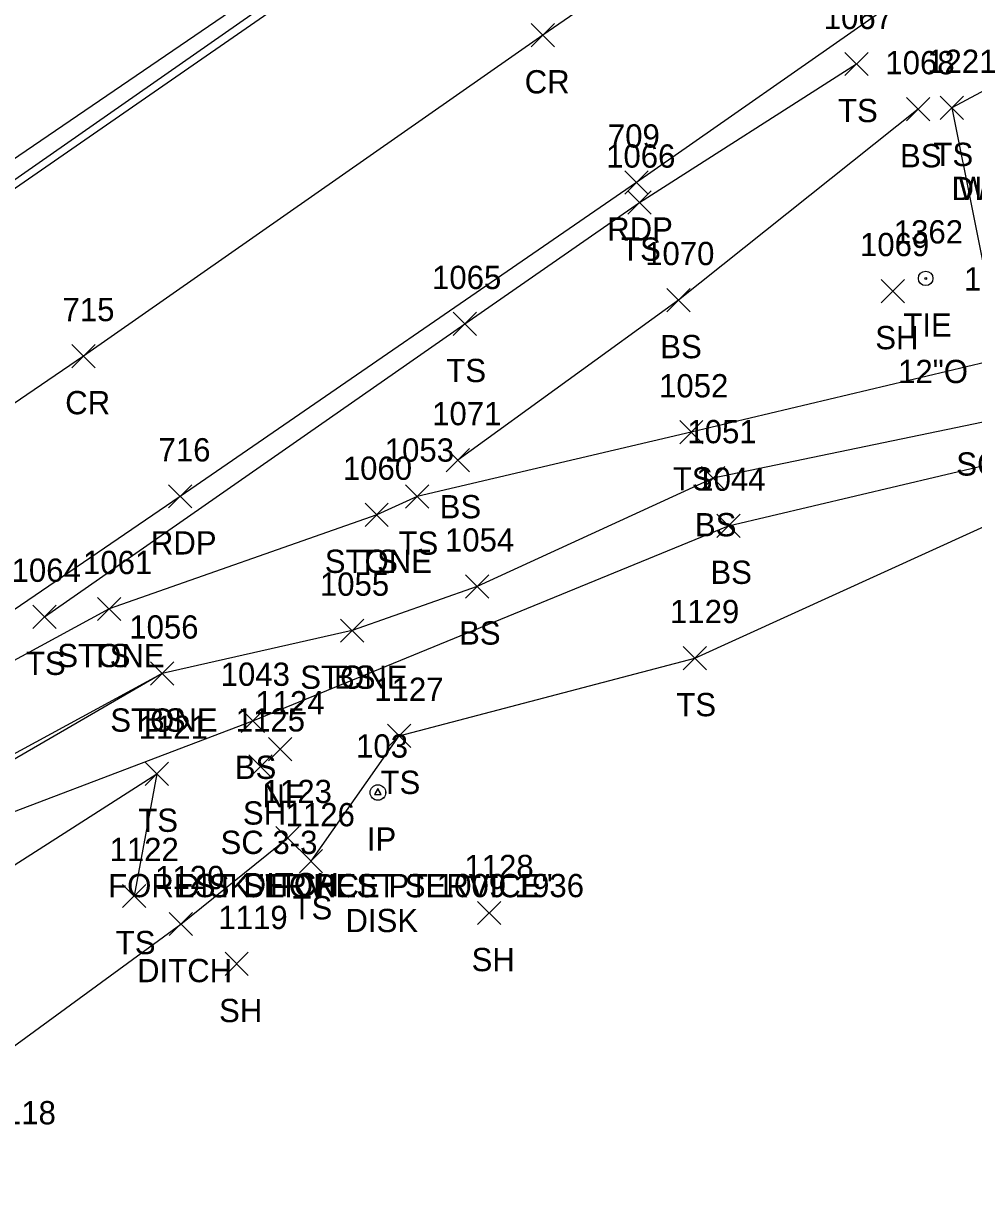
# Model space of a CAD drawing. Extents: x 1528286 to 1556263, y 492387 to 508952.
# Drawn here: x 1528862.6 to 1528944.2, y 492861.6 to 492961.3 of the extents above; entities that cross this region are included whole.
import ezdxf

# ---------------------------------------------------------------- set-up
doc = ezdxf.new("R2010")
doc.units = 0
for name, color, linetype in [('C_A', 7, 'Continuous'), ('C_C', 7, 'Continuous'), ('C_I', 7, 'Continuous'), ('CBP', 7, 'Continuous'), ('D_A', 7, 'Continuous'), ('D_I', 7, 'Continuous'), ('D_TIC', 7, 'Continuous'), ('DD', 7, 'Continuous'), ('L_A', 7, 'Continuous'), ('L_C', 7, 'Continuous'), ('L_I', 7, 'Continuous'), ('L_TIC', 7, 'Continuous'), ('LASF', 7, 'Continuous'), ('LELB', 7, 'Continuous'), ('M_A', 7, 'Continuous'), ('M_C', 7, 'Continuous'), ('M_I', 7, 'Continuous'), ('MPIR', 7, 'Continuous'), ('P_A', 7, 'Continuous'), ('P_I', 7, 'Continuous'), ('P_TIC', 7, 'Continuous'), ('PET', 7, 'Continuous'), ('PRC', 7, 'Continuous'), ('RGR', 7, 'Continuous')]:
    doc.layers.add(name, color=color, linetype=linetype)

msp = doc.modelspace()

# ---------------------------------------------------------------- linework, layer by layer
at = {"layer": 'CBP'}
for radius in [0.625, 0.625, 0.0833, 0.0833]:
    msp.add_circle((1528940.091, 492939.392), radius, dxfattribs=at)
at = {"layer": 'D_TIC'}
for points in [[(1528884.264, 492890.293), (1528886.264, 492892.293)], [(1528886.264, 492890.293), (1528884.264, 492892.293)], [(1528884.264, 492890.293), (1528886.264, 492892.293)], [(1528886.264, 492890.293), (1528884.264, 492892.293)], [(1528875.113, 492882.9), (1528877.113, 492884.9)], [(1528877.113, 492882.9), (1528875.113, 492884.9)], [(1528875.113, 492882.9), (1528877.113, 492884.9)], [(1528877.113, 492882.9), (1528875.113, 492884.9)]]:
    msp.add_lwpolyline(points, dxfattribs=at)
at = {"layer": 'DD'}
msp.add_lwpolyline([(1528821.309, 492845.775), (1528834.865, 492854.142), (1528847.183, 492864.422), (1528856.697, 492869.705), (1528876.113, 492883.9), (1528885.264, 492891.293)], dxfattribs=at)
msp.add_lwpolyline([(1528821.309, 492845.775), (1528834.865, 492854.142), (1528847.183, 492864.422), (1528856.697, 492869.705), (1528876.113, 492883.9), (1528885.264, 492891.293)], dxfattribs=at)
at = {"layer": 'L_TIC'}
for points in [[(1528933.15, 492956.819), (1528935.15, 492958.819)], [(1528935.15, 492956.819), (1528933.15, 492958.819)], [(1528933.15, 492956.819), (1528935.15, 492958.819)], [(1528935.15, 492956.819), (1528933.15, 492958.819)], [(1528938.445, 492952.934), (1528940.445, 492954.934)], [(1528940.445, 492952.934), (1528938.445, 492954.934)], [(1528938.445, 492952.934), (1528940.445, 492954.934)], [(1528940.445, 492952.934), (1528938.445, 492954.934)], [(1528941.345, 492953.048), (1528943.345, 492955.048)], [(1528943.345, 492953.048), (1528941.345, 492955.048)], [(1528941.345, 492953.048), (1528943.345, 492955.048)], [(1528943.345, 492953.048), (1528941.345, 492955.048)], [(1528914.515, 492944.908), (1528916.515, 492946.908)], [(1528916.515, 492944.908), (1528914.515, 492946.908)], [(1528914.515, 492944.908), (1528916.515, 492946.908)], [(1528916.515, 492944.908), (1528914.515, 492946.908)], [(1528917.851, 492936.528), (1528919.851, 492938.528)], [(1528919.851, 492936.528), (1528917.851, 492938.528)], [(1528917.851, 492936.528), (1528919.851, 492938.528)], [(1528919.851, 492936.528), (1528917.851, 492938.528)], [(1528936.271, 492937.301), (1528938.271, 492939.301)], [(1528938.271, 492937.301), (1528936.271, 492939.301)], [(1528936.271, 492937.301), (1528938.271, 492939.301)], [(1528938.271, 492937.301), (1528936.271, 492939.301)], [(1528899.505, 492934.476), (1528901.505, 492936.476)], [(1528901.505, 492934.476), (1528899.505, 492936.476)], [(1528899.505, 492934.476), (1528901.505, 492936.476)], [(1528901.505, 492934.476), (1528899.505, 492936.476)], [(1528918.959, 492925.163), (1528920.959, 492927.163)], [(1528920.959, 492925.163), (1528918.959, 492927.163)], [(1528918.959, 492925.163), (1528920.959, 492927.163)], [(1528920.959, 492925.163), (1528918.959, 492927.163)], [(1528898.899, 492922.769), (1528900.899, 492924.769)], [(1528900.899, 492922.769), (1528898.899, 492924.769)], [(1528898.899, 492922.769), (1528900.899, 492924.769)], [(1528900.899, 492922.769), (1528898.899, 492924.769)], [(1528920.827, 492921.221), (1528922.827, 492923.221)], [(1528922.827, 492921.221), (1528920.827, 492923.221)], [(1528920.827, 492921.221), (1528922.827, 492923.221)], [(1528922.827, 492921.221), (1528920.827, 492923.221)], [(1528895.398, 492919.638), (1528897.398, 492921.638)], [(1528897.398, 492919.638), (1528895.398, 492921.638)], [(1528895.398, 492919.638), (1528897.398, 492921.638)], [(1528897.398, 492919.638), (1528895.398, 492921.638)], [(1528891.931, 492918.077), (1528893.931, 492920.077)], [(1528893.931, 492918.077), (1528891.931, 492920.077)], [(1528891.931, 492918.077), (1528893.931, 492920.077)], [(1528893.931, 492918.077), (1528891.931, 492920.077)], [(1528891.931, 492918.077), (1528893.931, 492920.077)], [(1528893.931, 492918.077), (1528891.931, 492920.077)], [(1528891.931, 492918.077), (1528893.931, 492920.077)], [(1528893.931, 492918.077), (1528891.931, 492920.077)], [(1528922.156, 492917.133), (1528924.156, 492919.133)], [(1528924.156, 492917.133), (1528922.156, 492919.133)], [(1528922.156, 492917.133), (1528924.156, 492919.133)], [(1528924.156, 492917.133), (1528922.156, 492919.133)], [(1528900.569, 492911.915), (1528902.569, 492913.915)], [(1528902.569, 492911.915), (1528900.569, 492913.915)], [(1528900.569, 492911.915), (1528902.569, 492913.915)], [(1528902.569, 492911.915), (1528900.569, 492913.915)], [(1528868.957, 492909.976), (1528870.957, 492911.976)], [(1528870.957, 492909.976), (1528868.957, 492911.976)], [(1528868.957, 492909.976), (1528870.957, 492911.976)], [(1528870.957, 492909.976), (1528868.957, 492911.976)], [(1528868.957, 492909.976), (1528870.957, 492911.976)], [(1528870.957, 492909.976), (1528868.957, 492911.976)], [(1528868.957, 492909.976), (1528870.957, 492911.976)], [(1528870.957, 492909.976), (1528868.957, 492911.976)], [(1528863.389, 492909.31), (1528865.389, 492911.31)], [(1528865.389, 492909.31), (1528863.389, 492911.31)], [(1528863.389, 492909.31), (1528865.389, 492911.31)], [(1528865.389, 492909.31), (1528863.389, 492911.31)], [(1528889.826, 492908.115), (1528891.826, 492910.115)], [(1528891.826, 492908.115), (1528889.826, 492910.115)], [(1528889.826, 492908.115), (1528891.826, 492910.115)], [(1528891.826, 492908.115), (1528889.826, 492910.115)], [(1528889.826, 492908.115), (1528891.826, 492910.115)], [(1528891.826, 492908.115), (1528889.826, 492910.115)], [(1528889.826, 492908.115), (1528891.826, 492910.115)], [(1528891.826, 492908.115), (1528889.826, 492910.115)], [(1528919.262, 492905.759), (1528921.262, 492907.759)], [(1528921.262, 492905.759), (1528919.262, 492907.759)], [(1528919.262, 492905.759), (1528921.262, 492907.759)], [(1528921.262, 492905.759), (1528919.262, 492907.759)], [(1528873.507, 492904.431), (1528875.507, 492906.431)], [(1528875.507, 492904.431), (1528873.507, 492906.431)], [(1528873.507, 492904.431), (1528875.507, 492906.431)], [(1528875.507, 492904.431), (1528873.507, 492906.431)], [(1528873.507, 492904.431), (1528875.507, 492906.431)], [(1528875.507, 492904.431), (1528873.507, 492906.431)], [(1528873.507, 492904.431), (1528875.507, 492906.431)], [(1528875.507, 492904.431), (1528873.507, 492906.431)], [(1528881.303, 492900.371), (1528883.303, 492902.371)], [(1528883.303, 492900.371), (1528881.303, 492902.371)], [(1528881.303, 492900.371), (1528883.303, 492902.371)], [(1528883.303, 492900.371), (1528881.303, 492902.371)], [(1528893.852, 492899.077), (1528895.852, 492901.077)], [(1528895.852, 492899.077), (1528893.852, 492901.077)], [(1528893.852, 492899.077), (1528895.852, 492901.077)], [(1528895.852, 492899.077), (1528893.852, 492901.077)], [(1528883.638, 492897.92), (1528885.638, 492899.92)], [(1528885.638, 492897.92), (1528883.638, 492899.92)], [(1528883.638, 492897.92), (1528885.638, 492899.92)], [(1528885.638, 492897.92), (1528883.638, 492899.92)], [(1528881.95, 492896.447), (1528883.95, 492898.447)], [(1528883.95, 492896.447), (1528881.95, 492898.447)], [(1528881.95, 492896.447), (1528883.95, 492898.447)], [(1528883.95, 492896.447), (1528881.95, 492898.447)], [(1528873.04, 492895.82), (1528875.04, 492897.82)], [(1528875.04, 492895.82), (1528873.04, 492897.82)], [(1528873.04, 492895.82), (1528875.04, 492897.82)], [(1528875.04, 492895.82), (1528873.04, 492897.82)], [(1528886.291, 492888.3), (1528888.291, 492890.3)], [(1528888.291, 492888.3), (1528886.291, 492890.3)], [(1528886.291, 492888.3), (1528888.291, 492890.3)], [(1528888.291, 492888.3), (1528886.291, 492890.3)], [(1528871.111, 492885.309), (1528873.111, 492887.309)], [(1528873.111, 492885.309), (1528871.111, 492887.309)], [(1528871.111, 492885.309), (1528873.111, 492887.309)], [(1528873.111, 492885.309), (1528871.111, 492887.309)], [(1528901.596, 492883.846), (1528903.596, 492885.846)], [(1528903.596, 492883.846), (1528901.596, 492885.846)], [(1528901.596, 492883.846), (1528903.596, 492885.846)], [(1528903.596, 492883.846), (1528901.596, 492885.846)], [(1528879.904, 492879.468), (1528881.904, 492881.468)], [(1528881.904, 492879.468), (1528879.904, 492881.468)], [(1528879.904, 492879.468), (1528881.904, 492881.468)], [(1528881.904, 492879.468), (1528879.904, 492881.468)]]:
    msp.add_lwpolyline(points, dxfattribs=at)
at = {"layer": 'LASF'}
for points in [[(1528892.931, 492919.077), (1528869.957, 492910.976), (1528843.058, 492896.384), (1528834.233, 492890.275)], [(1528892.931, 492919.077), (1528869.957, 492910.976), (1528843.058, 492896.384), (1528834.233, 492890.275)], [(1528890.826, 492909.115), (1528874.507, 492905.431), (1528855.412, 492895.062), (1528834.233, 492890.275)], [(1528890.826, 492909.115), (1528874.507, 492905.431), (1528855.412, 492895.062), (1528834.233, 492890.275)]]:
    msp.add_lwpolyline(points, dxfattribs=at)
at = {"layer": 'LELB'}
for points in [[(1528511.531, 492702.846), (1528534.14, 492721.314), (1528572.642, 492751.164), (1528586.729, 492763.586), (1528600.497, 492766.346), (1528613.458, 492775.516), (1528652.2, 492802.526), (1528688.619, 492828.262), (1528710.289, 492843.118), (1528742.907, 492866.471), (1528778.713, 492891.266), (1528817.445, 492919.082), (1528857.746, 492946.937), (1528897.372, 492973.983), (1528940.286, 493003.739)], [(1528511.531, 492702.846), (1528534.14, 492721.314), (1528572.642, 492751.164), (1528586.729, 492763.586), (1528600.497, 492766.346), (1528613.458, 492775.516), (1528652.2, 492802.526), (1528688.619, 492828.262), (1528710.289, 492843.118), (1528742.907, 492866.471), (1528778.713, 492891.266), (1528817.445, 492919.082), (1528857.746, 492946.937), (1528897.372, 492973.983), (1528940.286, 493003.739)], [(1528956.74, 492935.404), (1528960.901, 492952.952), (1528952.193, 492959.33), (1528942.345, 492954.048), (1528946.075, 492935.347)], [(1528956.74, 492935.404), (1528960.901, 492952.952), (1528952.193, 492959.33), (1528942.345, 492954.048), (1528946.075, 492935.347)], [(1528864.389, 492910.31), (1528900.505, 492935.476), (1528915.515, 492945.908), (1528934.15, 492957.819)], [(1528864.389, 492910.31), (1528900.505, 492935.476), (1528915.515, 492945.908), (1528934.15, 492957.819)], [(1528939.445, 492953.934), (1528918.851, 492937.528), (1528899.899, 492923.769)], [(1528939.445, 492953.934), (1528918.851, 492937.528), (1528899.899, 492923.769)], [(1528946.969, 492932.586), (1528919.959, 492926.163), (1528896.398, 492920.638), (1528892.931, 492919.077), (1528869.957, 492910.976), (1528843.058, 492896.384), (1528834.233, 492890.275), (1528806.992, 492871.856), (1528782.492, 492854.983), (1528750.989, 492833.046), (1528710.78, 492805.361), (1528694.188, 492792.448), (1528682.217, 492773.575), (1528672.784, 492775.788)], [(1528946.969, 492932.586), (1528919.959, 492926.163), (1528896.398, 492920.638), (1528892.931, 492919.077), (1528869.957, 492910.976), (1528843.058, 492896.384), (1528834.233, 492890.275), (1528806.992, 492871.856), (1528782.492, 492854.983), (1528750.989, 492833.046), (1528710.78, 492805.361), (1528694.188, 492792.448), (1528682.217, 492773.575), (1528672.784, 492775.788)], [(1528950.166, 492932.924), (1528948.057, 492927.676), (1528921.827, 492922.221), (1528901.569, 492912.915), (1528890.826, 492909.115), (1528874.507, 492905.431), (1528854.678, 492893.942), (1528843.943, 492888.142)], [(1528950.166, 492932.924), (1528948.057, 492927.676), (1528921.827, 492922.221), (1528901.569, 492912.915), (1528890.826, 492909.115), (1528874.507, 492905.431), (1528854.678, 492893.942), (1528843.943, 492888.142)], [(1528851.535, 492889.673), (1528882.303, 492901.371), (1528923.156, 492918.133), (1528948.593, 492924.145), (1528953.496, 492933.309)], [(1528851.535, 492889.673), (1528882.303, 492901.371), (1528923.156, 492918.133), (1528948.593, 492924.145), (1528953.496, 492933.309)], [(1528887.291, 492889.3), (1528894.852, 492900.077), (1528920.262, 492906.759), (1528952.543, 492921.441)], [(1528887.291, 492889.3), (1528894.852, 492900.077), (1528920.262, 492906.759), (1528952.543, 492921.441)], [(1528771.365, 492833.538), (1528790.046, 492845.146), (1528813.011, 492860.356), (1528823.162, 492868.505), (1528838.745, 492881.757), (1528852.776, 492883.19), (1528874.04, 492896.82), (1528872.111, 492886.309)], [(1528771.365, 492833.538), (1528790.046, 492845.146), (1528813.011, 492860.356), (1528823.162, 492868.505), (1528838.745, 492881.757), (1528852.776, 492883.19), (1528874.04, 492896.82), (1528872.111, 492886.309)]]:
    msp.add_lwpolyline(points, dxfattribs=at)
at = {"layer": 'MPIR'}
for points in [[(1528893.036, 492895.533), (1528892.747, 492895.033), (1528893.324, 492895.033)], [(1528893.037, 492895.538), (1528892.748, 492895.038), (1528893.326, 492895.038)]]:
    msp.add_lwpolyline(points, close=True, dxfattribs=at)
for centre in [(1528893.036, 492895.2), (1528893.037, 492895.205)]:
    msp.add_circle(centre, 0.667, dxfattribs=at)
at = {"layer": 'P_TIC'}
for points in [[(1528906.211, 492959.288), (1528908.211, 492961.288)], [(1528908.211, 492959.288), (1528906.211, 492961.288)], [(1528906.211, 492959.288), (1528908.211, 492961.288)], [(1528908.211, 492959.288), (1528906.211, 492961.288)], [(1528914.24, 492946.631), (1528916.24, 492948.631)], [(1528916.24, 492946.631), (1528914.24, 492948.631)], [(1528914.24, 492946.631), (1528916.24, 492948.631)], [(1528916.24, 492946.631), (1528914.24, 492948.631)], [(1528866.742, 492931.713), (1528868.742, 492933.713)], [(1528868.742, 492931.713), (1528866.742, 492933.713)], [(1528866.742, 492931.713), (1528868.742, 492933.713)], [(1528868.742, 492931.713), (1528866.742, 492933.713)], [(1528875.045, 492919.659), (1528877.045, 492921.659)], [(1528877.045, 492919.659), (1528875.045, 492921.659)], [(1528875.045, 492919.659), (1528877.045, 492921.659)], [(1528877.045, 492919.659), (1528875.045, 492921.659)]]:
    msp.add_lwpolyline(points, dxfattribs=at)
at = {"layer": 'PET'}
for points in [[(1528941.998, 493002.12), (1528898.48, 492972.509), (1528859.279, 492945.341), (1528819.079, 492917.533), (1528787.553, 492894.483), (1528780.465, 492889.936), (1528744.229, 492865.118), (1528711.173, 492841.816), (1528689.558, 492826.658), (1528653.332, 492801.515)], [(1528941.998, 493002.12), (1528898.48, 492972.509), (1528859.279, 492945.341), (1528819.079, 492917.533), (1528787.553, 492894.483), (1528780.465, 492889.936), (1528744.229, 492865.118), (1528711.173, 492841.816), (1528689.558, 492826.658), (1528653.332, 492801.515)], [(1528958.712, 492978.015), (1528915.24, 492947.631), (1528876.045, 492920.659), (1528835.6, 492893.02)], [(1528958.712, 492978.015), (1528915.24, 492947.631), (1528876.045, 492920.659), (1528835.6, 492893.02)]]:
    msp.add_lwpolyline(points, dxfattribs=at)
at = {"layer": 'PRC'}
msp.add_lwpolyline([(1528950.02, 492989.767), (1528907.211, 492960.288), (1528867.742, 492932.713), (1528827.787, 492905.434)], dxfattribs=at)
msp.add_lwpolyline([(1528950.02, 492989.767), (1528907.211, 492960.288), (1528867.742, 492932.713), (1528827.787, 492905.434)], dxfattribs=at)
at = {"layer": 'RGR'}
msp.add_lwpolyline([(1528941.405, 493002.785), (1528898.116, 492973.218), (1528858.975, 492945.897), (1528818.829, 492918.12), (1528780.054, 492890.637), (1528744.146, 492865.314), (1528711.237, 492842.066), (1528689.599, 492826.87), (1528653.301, 492801.623)], dxfattribs=at)
msp.add_lwpolyline([(1528941.405, 493002.785), (1528898.116, 492973.218), (1528858.975, 492945.897), (1528818.829, 492918.12), (1528780.054, 492890.637), (1528744.146, 492865.314), (1528711.237, 492842.066), (1528689.599, 492826.87), (1528653.301, 492801.623)], dxfattribs=at)

# ---------------------------------------------------------------- texts
at = {"layer": 'C_A'}
msp.add_text('TIE', height=2, dxfattribs=at).set_placement((1528938.17, 492934.392))
msp.add_text('TIE', height=2, dxfattribs=at).set_placement((1528938.17, 492934.392))
at = {"layer": 'C_C'}
msp.add_text('12"O', height=2, dxfattribs=at).set_placement((1528937.721, 492930.392))
msp.add_text('12"O', height=2, dxfattribs=at).set_placement((1528937.721, 492930.392))
at = {"layer": 'C_I'}
msp.add_text('1362', height=2, dxfattribs=at).set_placement((1528937.351, 492942.392))
msp.add_text('1362', height=2, dxfattribs=at).set_placement((1528937.351, 492942.392))
at = {"layer": 'D_A'}
for p in [(1528881.5, 492886.293), (1528881.5, 492886.293), (1528872.349, 492878.9), (1528872.349, 492878.9)]:
    msp.add_text('DITCH', height=2, dxfattribs=at).set_placement(p)
at = {"layer": 'D_I'}
for s, p in [('1123', (1528883.138, 492894.293)), ('1123', (1528883.138, 492894.293)), ('1120', (1528873.9, 492886.9)), ('1120', (1528873.9, 492886.9))]:
    msp.add_text(s, height=2, dxfattribs=at).set_placement(p)
at = {"layer": 'L_A'}
for s, p in [('TS', (1528932.559, 492952.819)), ('TS', (1528932.559, 492952.819)), ('BS', (1528937.886, 492948.934)), ('BS', (1528937.886, 492948.934)), ('TS', (1528940.754, 492949.048)), ('TS', (1528940.754, 492949.048)), ('TS', (1528913.925, 492940.908)), ('TS', (1528913.925, 492940.908)), ('SH', (1528935.76, 492933.301)), ('SH', (1528935.76, 492933.301)), ('BS', (1528917.292, 492932.528)), ('BS', (1528917.292, 492932.528)), ('TS', (1528898.914, 492930.476)), ('TS', (1528898.914, 492930.476)), ('TS', (1528918.369, 492921.163)), ('TS', (1528918.369, 492921.163)), ('BS', (1528898.34, 492918.769)), ('BS', (1528898.34, 492918.769)), ('BS', (1528920.268, 492917.221)), ('BS', (1528920.268, 492917.221)), ('TS', (1528894.807, 492915.638)), ('TS', (1528894.807, 492915.638)), ('STONE', (1528888.474, 492914.077)), ('STONE', (1528888.474, 492914.077)), ('TS', (1528891.34, 492914.077)), ('TS', (1528891.34, 492914.077)), ('BS', (1528921.597, 492913.133)), ('BS', (1528921.597, 492913.133)), ('BS', (1528900.01, 492907.915)), ('BS', (1528900.01, 492907.915)), ('STONE', (1528865.5, 492905.976)), ('STONE', (1528865.5, 492905.976)), ('TS', (1528868.366, 492905.976)), ('TS', (1528868.366, 492905.976)), ('TS', (1528862.799, 492905.31)), ('TS', (1528862.799, 492905.31)), ('STONE', (1528886.369, 492904.115)), ('STONE', (1528886.369, 492904.115)), ('BS', (1528889.267, 492904.115)), ('BS', (1528889.267, 492904.115)), ('TS', (1528918.671, 492901.759)), ('TS', (1528918.671, 492901.759)), ('STONE', (1528870.05, 492900.431)), ('STONE', (1528870.05, 492900.431)), ('BS', (1528872.948, 492900.431)), ('BS', (1528872.948, 492900.431)), ('BS', (1528880.744, 492896.371)), ('BS', (1528880.744, 492896.371)), ('TS', (1528893.261, 492895.077)), ('TS', (1528893.261, 492895.077)), ('NF', (1528883.119, 492893.92)), ('NF', (1528883.119, 492893.92)), ('SH', (1528881.439, 492892.447)), ('SH', (1528881.439, 492892.447)), ('TS', (1528872.45, 492891.82)), ('TS', (1528872.45, 492891.82)), ('TS', (1528885.701, 492884.3)), ('TS', (1528885.701, 492884.3)), ('TS', (1528870.52, 492881.309)), ('TS', (1528870.52, 492881.309)), ('SH', (1528901.084, 492879.846)), ('SH', (1528901.084, 492879.846)), ('SH', (1528879.392, 492875.468)), ('SH', (1528879.392, 492875.468))]:
    msp.add_text(s, height=2, dxfattribs=at).set_placement(p)
at = {"layer": 'L_C'}
for s, p in [('SC 3-2', (1528942.715, 492922.441)), ('SC 3-2', (1528942.715, 492922.441)), ('SC 3-3', (1528879.52, 492889.92)), ('SC 3-3', (1528879.52, 492889.92))]:
    msp.add_text(s, height=2, dxfattribs=at).set_placement(p)
at = {"layer": 'L_I'}
for s, p in [('1067', (1528931.331, 492960.819)), ('1067', (1528931.331, 492960.819)), ('1068', (1528936.626, 492956.934)), ('1068', (1528936.626, 492956.934)), ('1221', (1528940.219, 492957.048)), ('1221', (1528940.219, 492957.048)), ('1066', (1528912.641, 492948.908)), ('1066', (1528912.641, 492948.908)), ('1069', (1528934.445, 492941.301)), ('1069', (1528934.445, 492941.301)), ('1070', (1528915.993, 492940.528)), ('1070', (1528915.993, 492940.528)), ('1065', (1528897.686, 492938.476)), ('1065', (1528897.686, 492938.476)), ('1222', (1528943.383, 492938.347)), ('1222', (1528943.383, 492938.347)), ('1052', (1528917.188, 492929.163)), ('1052', (1528917.188, 492929.163)), ('1071', (1528897.695, 492926.769)), ('1071', (1528897.695, 492926.769)), ('1051', (1528919.623, 492925.221)), ('1051', (1528919.623, 492925.221)), ('1053', (1528893.626, 492923.638)), ('1053', (1528893.626, 492923.638)), ('1060', (1528890.025, 492922.077)), ('1060', (1528890.025, 492922.077)), ('1060', (1528890.025, 492922.077)), ('1060', (1528890.025, 492922.077)), ('1044', (1528920.384, 492921.133)), ('1044', (1528920.384, 492921.133)), ('1054', (1528898.797, 492915.915)), ('1054', (1528898.797, 492915.915)), ('1061', (1528867.705, 492913.976)), ('1061', (1528867.705, 492913.976)), ('1061', (1528867.705, 492913.976)), ('1061', (1528867.705, 492913.976)), ('1064', (1528861.57, 492913.31)), ('1064', (1528861.57, 492913.31)), ('1055', (1528888.054, 492912.115)), ('1055', (1528888.054, 492912.115)), ('1055', (1528888.054, 492912.115)), ('1055', (1528888.054, 492912.115)), ('1129', (1528918.128, 492909.759)), ('1129', (1528918.128, 492909.759)), ('1056', (1528871.68, 492908.431)), ('1056', (1528871.68, 492908.431)), ('1056', (1528871.68, 492908.431)), ('1056', (1528871.68, 492908.431)), ('1043', (1528879.531, 492904.371)), ('1043', (1528879.531, 492904.371)), ('1127', (1528892.726, 492903.077)), ('1127', (1528892.726, 492903.077)), ('1124', (1528882.512, 492901.92)), ('1124', (1528882.512, 492901.92)), ('1125', (1528880.824, 492900.447)), ('1125', (1528880.824, 492900.447)), ('1121', (1528872.481, 492899.82)), ('1121', (1528872.481, 492899.82)), ('1126', (1528885.11, 492892.3)), ('1126', (1528885.11, 492892.3)), ('1122', (1528869.985, 492889.309)), ('1122', (1528869.985, 492889.309)), ('1128', (1528900.47, 492887.846)), ('1128', (1528900.47, 492887.846)), ('1119', (1528879.337, 492883.468)), ('1119', (1528879.337, 492883.468)), ('1118', (1528859.427, 492866.683)), ('1118', (1528859.427, 492866.683))]:
    msp.add_text(s, height=2, dxfattribs=at).set_placement(p)
at = {"layer": 'M_A'}
for p in [(1528892.083, 492890.2), (1528892.084, 492890.205)]:
    msp.add_text('IP', height=2, dxfattribs=at).set_placement(p)
at = {"layer": 'M_C'}
for s, p in [('DISK "PROPERTY BOUNDARY"', (1528942.307, 492946.121)), ('WITNESS COR26 N11W 22.68', (1528942.921, 492946.121)), ('FOREST SERVICE PT 1009 1936', (1528869.864, 492886.205)), ('DISK "FOREST SERVICE"', (1528875.823, 492886.2)), ('DISK', (1528890.249, 492883.205))]:
    msp.add_text(s, height=2, dxfattribs=at).set_placement(p)
at = {"layer": 'M_I'}
for p in [(1528891.162, 492898.2), (1528891.163, 492898.205)]:
    msp.add_text('103', height=2, dxfattribs=at).set_placement(p)
at = {"layer": 'P_A'}
for s, p in [('CR', (1528905.644, 492955.288)), ('CR', (1528905.644, 492955.288)), ('RDP', (1528912.728, 492942.631)), ('RDP', (1528912.728, 492942.631)), ('CR', (1528866.175, 492927.713)), ('CR', (1528866.175, 492927.713)), ('RDP', (1528873.533, 492915.659)), ('RDP', (1528873.533, 492915.659))]:
    msp.add_text(s, height=2, dxfattribs=at).set_placement(p)
at = {"layer": 'P_I'}
for s, p in [('709', (1528912.791, 492950.631)), ('709', (1528912.791, 492950.631)), ('715', (1528865.946, 492935.713)), ('715', (1528865.946, 492935.713)), ('716', (1528874.195, 492923.659)), ('716', (1528874.195, 492923.659))]:
    msp.add_text(s, height=2, dxfattribs=at).set_placement(p)

doc.saveas('drawing.dxf')
